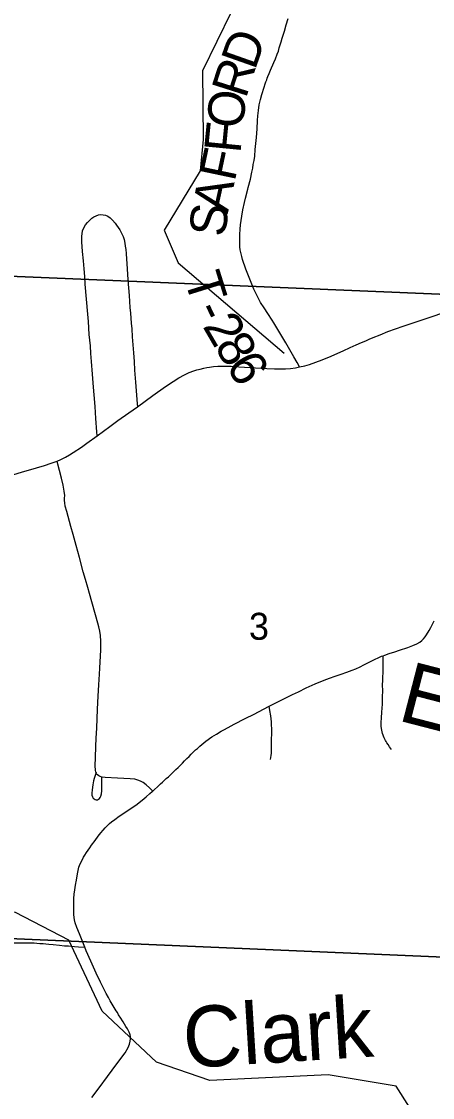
# Model space of a CAD drawing. Extents: x 0 to 34, y 0 to 22.
# Drawn here: x 5.267 to 5.906, y 17.749 to 19.422 of the extents above; entities that cross this region are included whole.
import ezdxf

# ---------------------------------------------------------------- set-up
doc = ezdxf.new("R2010")
doc.units = 0
for name, color, linetype in [('GM_X_County_Road', 7, 'Continuous'), ('GM_X_Minor_River', 7, 'Continuous'), ('GM_X_Minor_River_Text', 7, 'Continuous'), ('GM_X_Section', 7, 'Continuous'), ('GM_X_Section_Text', 7, 'Continuous'), ('GM_X_State_Route', 7, 'Continuous'), ('GM_X_Township_Road', 7, 'Continuous'), ('GM_X_Township_Road_Text', 7, 'Continuous')]:
    doc.layers.add(name, color=color, linetype=linetype)

msp = doc.modelspace()

# ---------------------------------------------------------------- linework, layer by layer
at = {"layer": 'GM_X_County_Road'}
for points in [[(5.3702, 18.542), (5.3666, 18.5545), (5.3634, 18.5663), (5.3574, 18.5884), (5.3522, 18.6073), (5.3477, 18.624), (5.3442, 18.6366), (5.3376, 18.6599), (5.3354, 18.6684), (5.3345, 18.6733), (5.3342, 18.6771), (5.3344, 18.6809), (5.3346, 18.6851), (5.3339, 18.6918), (5.3323, 18.7008), (5.3297, 18.7117), (5.3266, 18.7239), (5.324, 18.7338), (5.3226, 18.7383)], [(5.4712, 18.2254), (5.4661, 18.2303), (5.4613, 18.235), (5.4564, 18.2386), (5.4522, 18.241), (5.4483, 18.2426), (5.4436, 18.2438), (5.4363, 18.2446), (5.4165, 18.2456), (5.3972, 18.2463), (5.3928, 18.2468), (5.3921, 18.2471), (5.3897, 18.2478), (5.3873, 18.2491), (5.3853, 18.2508), (5.384, 18.2524), (5.3832, 18.2541), (5.3829, 18.2549), (5.3821, 18.2581), (5.3818, 18.2644), (5.3823, 18.2775), (5.383, 18.2949), (5.3836, 18.3079), (5.3845, 18.3234), (5.3857, 18.3525), (5.3867, 18.373), (5.3876, 18.3904), (5.3886, 18.4071), (5.389, 18.4164), (5.3904, 18.4449), (5.3905, 18.4585), (5.39, 18.4671), (5.389, 18.4738), (5.3873, 18.4805), (5.3859, 18.4864), (5.3729, 18.5324), (5.3702, 18.542)], [(5.3522, 18.0844), (5.3548, 18.0996), (5.3566, 18.107), (5.3586, 18.1123), (5.3619, 18.119), (5.3639, 18.1229), (5.3658, 18.126), (5.3684, 18.1299), (5.371, 18.1337), (5.3733, 18.1371), (5.3763, 18.1412), (5.3819, 18.1487), (5.3866, 18.1553), (5.3905, 18.1604), (5.3941, 18.1647), (5.3974, 18.1683), (5.3999, 18.171), (5.4041, 18.1749), (5.4074, 18.1776), (5.4122, 18.1814), (5.4191, 18.1865), (5.4295, 18.1932), (5.4469, 18.2053), (5.4503, 18.2078), (5.4547, 18.2113), (5.4609, 18.2163), (5.467, 18.2215), (5.4706, 18.2248), (5.4712, 18.2254), (5.4815, 18.2348), (5.4833, 18.2365), (5.4865, 18.2395), (5.4893, 18.2419), (5.4924, 18.2448), (5.4956, 18.2477), (5.4979, 18.2498), (5.501, 18.2528), (5.5046, 18.2563), (5.5072, 18.2588), (5.5107, 18.2623), (5.5138, 18.2654), (5.5173, 18.2689), (5.5208, 18.2724), (5.5242, 18.276), (5.5278, 18.2794), (5.5312, 18.283), (5.5349, 18.2863), (5.538, 18.2893), (5.5407, 18.2918), (5.5443, 18.2952), (5.5539, 18.3032), (5.5632, 18.3095), (5.5703, 18.3139), (5.5775, 18.3184), (5.5817, 18.3207), (5.5883, 18.3244), (5.5979, 18.3296), (5.6147, 18.3382), (5.6287, 18.3451), (5.6513, 18.3568), (5.6522, 18.3573), (5.6648, 18.3634), (5.6771, 18.3699), (5.6884, 18.3756), (5.6976, 18.3799), (5.7099, 18.3857), (5.7237, 18.3919), (5.7404, 18.3988), (5.7474, 18.4014), (5.7531, 18.4036), (5.7592, 18.4057), (5.7642, 18.4073), (5.773, 18.4101), (5.7811, 18.4131), (5.787, 18.4156), (5.7936, 18.4184), (5.7994, 18.4215), (5.8045, 18.4241), (5.8106, 18.4272), (5.8168, 18.4302), (5.8216, 18.4324), (5.827, 18.4349), (5.8292, 18.4357), (5.8318, 18.4366), (5.8387, 18.439), (5.8474, 18.4419), (5.8547, 18.4442), (5.8677, 18.4485), (5.8757, 18.4516), (5.8819, 18.4543), (5.8861, 18.4567), (5.8893, 18.4593), (5.892, 18.4621), (5.8944, 18.4652), (5.8966, 18.4682), (5.9008, 18.475), (5.9034, 18.4799), (5.9084, 18.4899)], [(5.3769, 17.7491), (5.388, 17.7639), (5.4008, 17.7816), (5.4154, 17.8013), (5.4282, 17.8185), (5.4329, 17.8269), (5.4353, 17.8321), (5.4363, 17.8364), (5.4366, 17.8404), (5.4366, 17.8438), (5.4363, 17.8464), (5.4357, 17.8479), (5.4346, 17.8509), (5.4322, 17.8557), (5.4297, 17.8595), (5.4274, 17.863), (5.4251, 17.8668), (5.4206, 17.8741), (5.4192, 17.8762), (5.4183, 17.8778), (5.4164, 17.881), (5.4147, 17.8836), (5.4084, 17.8942), (5.4051, 17.8996), (5.4024, 17.9046), (5.3991, 17.9106), (5.3902, 17.9283), (5.3835, 17.9424), (5.3749, 17.961), (5.368, 17.9769), (5.3657, 17.9826), (5.3645, 17.9856), (5.3574, 18.0035), (5.3535, 18.0133), (5.351, 18.0204), (5.3498, 18.0253), (5.3489, 18.0328), (5.3486, 18.0422), (5.3488, 18.0584), (5.3493, 18.0652), (5.3518, 18.0825), (5.3522, 18.0844)]]:
    msp.add_lwpolyline(points, dxfattribs=at)
at = {"layer": 'GM_X_Minor_River'}
for points in [[(5.5931, 19.4364), (5.5484, 19.3449), (5.5498, 19.2383), (5.5448, 19.1897), (5.489, 19.0973), (5.5106, 19.0463), (5.6753, 18.9062)], [(5.8908, 17.7015), (5.8497, 17.7665), (5.744, 17.7845), (5.5599, 17.7756), (5.4772, 17.8041), (5.3926, 17.8831), (5.3411, 17.9938), (5.2581, 18.0364), (5.2463, 18.0393), (5.0719, 17.9971), (4.976, 17.9568), (4.9029, 17.8836), (4.8524, 17.7955), (4.8044, 17.7841), (4.7571, 17.7969), (4.7005, 17.8898)]]:
    msp.add_lwpolyline(points, dxfattribs=at)
at = {"layer": 'GM_X_Section'}
for points in [[(6.2522, 20.0112), (6.1895, 18.9865), (5.1485, 19.0298), (5.159, 19.2125), (5.1842, 19.6356), (5.2086, 20.056)], [(5.1485, 19.0298), (6.1895, 18.9865), (6.1775, 18.7705), (6.1627, 18.5214), (6.1439, 18.2043), (6.1294, 17.9583), (5.0782, 18.0036), (5.1344, 18.7947)], [(5.0782, 18.0036), (6.1294, 17.9583), (6.1188, 17.7931), (6.0808, 17.1618), (6.0674, 16.9363), (5.0081, 16.9831)]]:
    msp.add_lwpolyline(points, close=True, dxfattribs=at)
at = {"layer": 'GM_X_State_Route'}
for points in [[(5.7384, 18.8973), (5.7451, 18.9001), (5.7672, 18.9099), (5.7783, 18.9148), (5.7876, 18.9188), (5.7959, 18.9225), (5.8024, 18.9254), (5.8075, 18.9276), (5.8137, 18.9304), (5.8247, 18.9348), (5.8366, 18.9396), (5.8605, 18.9483), (5.9007, 18.9615), (5.9543, 18.9796)], [(5.2552, 18.7173), (5.2675, 18.7209), (5.2909, 18.7276), (5.3033, 18.7314), (5.3136, 18.7349), (5.3226, 18.7383), (5.3283, 18.7408), (5.3356, 18.7444), (5.3417, 18.7479), (5.3478, 18.7517), (5.3604, 18.7601), (5.369, 18.7662), (5.385, 18.7778), (5.4047, 18.7921), (5.4172, 18.8012), (5.4343, 18.8135), (5.4474, 18.8228), (5.4715, 18.8404), (5.4909, 18.8541), (5.5031, 18.8622), (5.5118, 18.8679), (5.5207, 18.8725), (5.528, 18.8758), (5.535, 18.8784), (5.5399, 18.88), (5.5451, 18.8814), (5.5505, 18.8826), (5.5556, 18.8837), (5.5594, 18.8844), (5.5659, 18.8852), (5.5726, 18.8858), (5.5777, 18.886), (5.5843, 18.8861), (5.593, 18.8857), (5.6049, 18.8851), (5.6488, 18.8822), (5.6604, 18.8816), (5.6695, 18.8815), (5.6777, 18.8818), (5.6855, 18.8824), (5.693, 18.8834), (5.6993, 18.8846), (5.7075, 18.8865), (5.7151, 18.8887), (5.7248, 18.892), (5.7345, 18.8957), (5.7384, 18.8973)]]:
    msp.add_lwpolyline(points, dxfattribs=at)
at = {"layer": 'GM_X_Township_Road'}
for points in [[(5.6191, 19.161), (5.6198, 19.1638), (5.623, 19.1764), (5.6254, 19.1872), (5.6266, 19.1936), (5.6276, 19.1991), (5.6288, 19.2054), (5.6298, 19.2125), (5.6307, 19.2229), (5.6326, 19.2411), (5.6336, 19.2546), (5.6343, 19.268), (5.6348, 19.2748), (5.6356, 19.2834), (5.6369, 19.292), (5.6386, 19.3005), (5.6407, 19.3083), (5.6443, 19.3194), (5.6462, 19.3247), (5.6472, 19.3276), (5.6485, 19.3311), (5.6493, 19.3334), (5.6504, 19.3364), (5.6522, 19.341), (5.6543, 19.3462), (5.6595, 19.3578), (5.6622, 19.3637), (5.6649, 19.3709), (5.6665, 19.3757), (5.6678, 19.3808), (5.6707, 19.3902), (5.6724, 19.3955), (5.6758, 19.4068), (5.6789, 19.4162), (5.682, 19.4263)], [(5.6593, 18.9532), (5.6567, 18.9575), (5.6499, 18.9678), (5.6442, 18.9767), (5.639, 18.9851), (5.6351, 18.9922), (5.6286, 19.0055), (5.6263, 19.0106), (5.622, 19.0209), (5.6181, 19.0314), (5.6162, 19.0366), (5.6108, 19.0517), (5.6095, 19.0563), (5.6085, 19.0606), (5.6073, 19.0667), (5.6068, 19.0716), (5.6064, 19.0756), (5.6064, 19.0794), (5.6068, 19.0903), (5.6072, 19.0987), (5.6077, 19.1058), (5.6086, 19.1125), (5.6096, 19.1192), (5.6114, 19.129), (5.6138, 19.1405), (5.6154, 19.1471), (5.6191, 19.161)], [(5.385, 18.7778), (5.3846, 18.7838), (5.383, 18.8044), (5.3817, 18.8232), (5.3802, 18.8415), (5.3793, 18.853), (5.3777, 18.8736), (5.3763, 18.8931), (5.3753, 18.9056), (5.3744, 18.9174), (5.3727, 18.9353), (5.3714, 18.9552), (5.3705, 18.9667), (5.3665, 19.0134), (5.3656, 19.0251), (5.3647, 19.0374), (5.3636, 19.0497), (5.3624, 19.0639), (5.3613, 19.0792), (5.3611, 19.0855), (5.3611, 19.088), (5.3614, 19.0918), (5.3622, 19.0961), (5.364, 19.1009), (5.3666, 19.1054), (5.3698, 19.1093), (5.3724, 19.112), (5.3768, 19.1157), (5.3799, 19.1178), (5.3833, 19.1196), (5.387, 19.1209), (5.3908, 19.1214), (5.3941, 19.1213), (5.3978, 19.1204), (5.4013, 19.1188), (5.405, 19.1162), (5.4087, 19.1128), (5.4129, 19.1081), (5.4151, 19.1051), (5.4176, 19.1016), (5.42, 19.098), (5.423, 19.0926), (5.4253, 19.0875), (5.4267, 19.0828), (5.428, 19.0773), (5.4286, 19.0724), (5.4293, 19.0673), (5.4298, 19.0608), (5.4304, 19.0522), (5.4309, 19.0456), (5.4321, 19.0283), (5.4331, 19.0134), (5.4336, 19.0079), (5.4345, 18.9955), (5.4357, 18.9773), (5.4366, 18.9683), (5.4373, 18.9607), (5.438, 18.9525), (5.4387, 18.9441), (5.4395, 18.9317), (5.4404, 18.9188), (5.4414, 18.9065), (5.4423, 18.893), (5.4432, 18.8795), (5.4445, 18.8612), (5.447, 18.8274), (5.4474, 18.8228)], [(5.6993, 18.8846), (5.6956, 18.8915), (5.6907, 18.9006), (5.6782, 18.9219), (5.6655, 18.9427), (5.6593, 18.9532)], [(5.8424, 18.2898), (5.8394, 18.294), (5.8369, 18.2979), (5.8352, 18.3003), (5.8339, 18.3023), (5.833, 18.3039), (5.8309, 18.3084), (5.8285, 18.3148), (5.8271, 18.3202), (5.8264, 18.3257), (5.8263, 18.3319), (5.8268, 18.3394), (5.8275, 18.348), (5.8285, 18.3603), (5.8286, 18.3717), (5.8288, 18.3814), (5.8285, 18.3906), (5.8287, 18.3974), (5.8293, 18.4147), (5.8293, 18.4289), (5.8292, 18.4357)], [(5.6543, 18.2743), (5.655, 18.2777), (5.6554, 18.2807), (5.6557, 18.2844), (5.6561, 18.3032), (5.6562, 18.3175), (5.6557, 18.333), (5.6549, 18.3422), (5.6534, 18.3508), (5.6522, 18.3573)], [(5.3832, 18.2541), (5.3813, 18.248), (5.3803, 18.2448), (5.3794, 18.2411), (5.3784, 18.2352), (5.377, 18.2271), (5.3766, 18.2221), (5.3769, 18.219), (5.3776, 18.2167), (5.3788, 18.2145), (5.3802, 18.2132), (5.3818, 18.2123), (5.3836, 18.2119), (5.3854, 18.212), (5.3871, 18.2126), (5.3886, 18.2138), (5.3898, 18.2152), (5.3907, 18.2175), (5.3917, 18.221), (5.3922, 18.2259), (5.3923, 18.2321), (5.392, 18.2372), (5.392, 18.2407), (5.3921, 18.2471)], [(5.2507, 17.9897), (5.268, 17.9893), (5.2725, 17.9895), (5.2773, 17.9893), (5.2835, 17.9894), (5.2872, 17.9893), (5.2914, 17.989), (5.2956, 17.9886), (5.301, 17.9883), (5.3054, 17.9879), (5.3096, 17.9874), (5.3164, 17.9867), (5.3262, 17.9857), (5.3343, 17.9851), (5.3405, 17.9846), (5.3448, 17.9842), (5.3495, 17.9839), (5.3559, 17.9834), (5.3657, 17.9826)]]:
    msp.add_lwpolyline(points, dxfattribs=at)

# ---------------------------------------------------------------- texts
at = {"layer": 'GM_X_Minor_River_Text'}
for s, rotation, p in [('Evans', 345.5114, (5.8496, 18.3359)), ('Clark', 3.5111, (5.521, 17.7947))]:
    msp.add_text(s, height=0.0947, rotation=rotation, dxfattribs=at).set_placement(p)
at = {"layer": 'GM_X_Section_Text'}
msp.add_text('3', height=0.0419, rotation=0, dxfattribs=at).set_placement((5.6208, 18.4606))
at = {"layer": 'GM_X_Township_Road_Text'}
for s, rotation, p in [('D', 70.5743, (5.6299, 19.3446)), ('R', 72.35, (5.6159, 19.3005)), ('O', 83.9197, (5.6112, 19.2538)), ('F', 84.4202, (5.6075, 19.2158)), ('F', 78.1009, (5.5986, 19.1715)), ('A', 77.6506, (5.5878, 19.1222)), ('S', 84.2795, (5.5842, 19.0857)), ('T', 287.2883, (5.5198, 19.0224)), ('2', 300.1787, (5.5481, 18.948)), ('-', 295.5151, (5.5357, 18.9735)), ('8', 300.8467, (5.5661, 18.9171)), ('6', 301.0714, (5.5842, 18.8869))]:
    msp.add_text(s, height=0.0568, rotation=rotation, dxfattribs=at).set_placement(p)

doc.saveas('drawing.dxf')
